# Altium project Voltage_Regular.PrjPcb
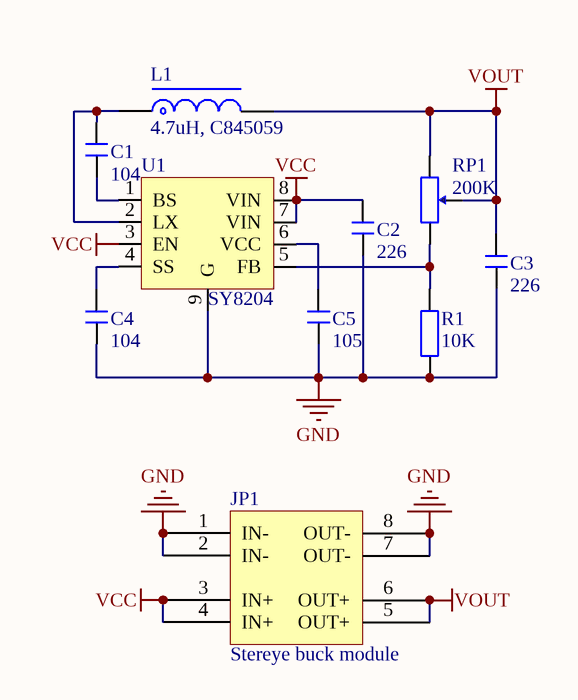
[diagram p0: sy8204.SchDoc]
1 sheet, 10 parts. Net scope: global (net labels, ports and power ports of the same name join across sheets).
Board file: VR.PcbDoc

## Sheet sy8204.SchDoc
size A4; SheetNumber: 1; SheetTotal: 1

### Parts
C1  104  [C 0603_L]
C2  226  [C 1206_L]
C3  226  [C 0805_L]
C4  104  [C 0603_L]
C5  105  [C 0603_L]
JP1  Stereye buck module  [Stereye buck module]
L1  4.7uH, C845059  [NR8040]
R1  10K  [R 0603_L]
RP1  200K  [3303W]
U1  SY8204  [ESOP8_N]

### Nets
GND: C2.1 C3.1 C4.1 C5.1 JP1.1(IN-) JP1.2(IN-) JP1.7(OUT-) JP1.8(OUT-) R1.1 U1.9(G)
VCC: C2.2 JP1.3(IN+) JP1.4(IN+) U1.3(EN) U1.7(VIN) U1.8(VIN)
VOUT: C3.2 JP1.5(OUT+) JP1.6(OUT+) L1.2 RP1.1 RP1.2
NetC1_1: C1.1 L1.1 U1.2(LX)
NetC1_2: C1.2 U1.1(BS)
NetC4_2: C4.2 U1.4(SS)
NetC5_2: C5.2 U1.6(VCC)
NetR1_2: R1.2 RP1.3 U1.5(FB)

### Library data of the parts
C1-C5 = C: 贴片电容; BOM名称: 无极性贴片电容; 淘宝ID: 封装库来自淘宝 ID：黄晶宝石
L1 = L-NR: NR磁胶电感; 版权归属: 来自淘宝 ID：黄晶宝石
R1 = R: 贴片电阻; 版权归属: 来自淘宝 ID：黄晶宝石
RP1 = RP-SMD: 贴片电位器; 版权归属: 封装库来自淘宝 ID：黄晶宝石
U1 = SY8204: 4.4-30V in, 4A out.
